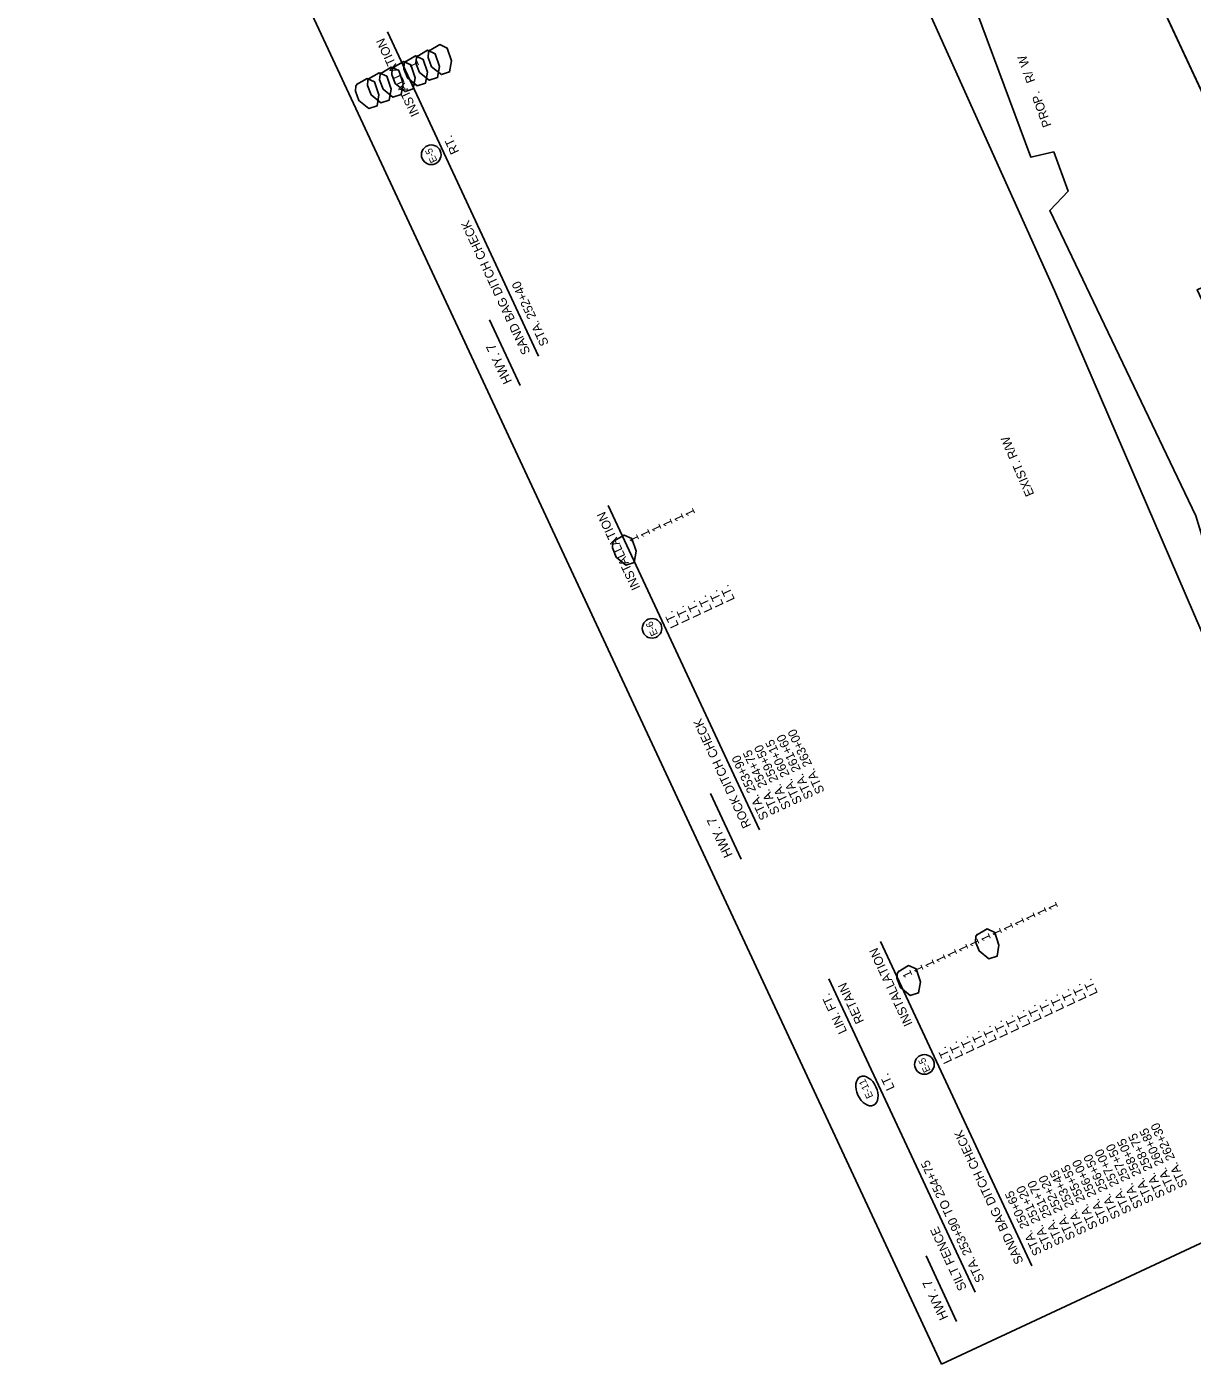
# Model space of a CAD drawing. Extents: x 964229 to 965790, y 1899262 to 1901149.
# Drawn here: x 964229 to 965014, y 1899262 to 1900163 of the extents above; entities that cross this region are included whole.
import ezdxf

# ---------------------------------------------------------------- set-up
doc = ezdxf.new("R2010")
doc.units = 0
for name, color, linetype in [('1', 7, 'Continuous'), ('44', 7, 'Continuous'), ('NO PLOT', 7, 'Continuous'), ('R_Draft', 7, 'Continuous'), ('S_TREE', 7, 'Continuous')]:
    doc.layers.add(name, color=color, linetype=linetype)

msp = doc.modelspace()

# ---------------------------------------------------------------- linework, layer by layer
at = {"layer": '1'}
msp.add_line((965070.98, 1900011.03), (964950.03, 1900270.4), dxfattribs=at)
for centre in [(964501.4, 1900076.83), (964650.13, 1899757.88), (964833.6, 1899464.18)]:
    msp.add_circle(centre, 6.61, dxfattribs=at)
msp.add_ellipse((964794.89, 1899446.28), major_axis=(-4.45, 9.53), ratio=0.638788, dxfattribs=at)
at = {"layer": '44'}
for p, q in [((964573.73, 1899941.19), (964471.87, 1900159.61)), ((964561.33, 1899921.41), (964540.69, 1899965.68)), ((964722.46, 1899622.24), (964620.6, 1899840.66)), ((964710.06, 1899602.46), (964689.42, 1899646.73)), ((964905.93, 1899328.54), (964804.07, 1899546.97)), ((964867.72, 1899310.72), (964769.33, 1899521.71)), ((964855.32, 1899290.95), (964834.68, 1899335.21))]:
    msp.add_line(p, q, dxfattribs=at)
at = {"layer": 'NO PLOT'}
for points in [[(965789.77, 1899702.74), (965115.54, 1901148.63), (964643.21, 1900928.38), (964770.42, 1900655.58), (964831.6, 1900684.11), (965011.21, 1900298.93), (964950.03, 1900270.4), (965070.98, 1900011.03), (965126.95, 1900037.14), (965271.77, 1899726.58), (965215.79, 1899700.48), (965317.44, 1899482.49)], [(965789.77, 1899702.74), (965115.54, 1901148.63), (964643.21, 1900928.38), (964770.42, 1900655.58), (964831.6, 1900684.11), (965011.21, 1900298.93), (964950.03, 1900270.4), (965070.98, 1900011.03), (965126.95, 1900037.14), (965271.77, 1899726.58), (965215.79, 1899700.48), (965317.44, 1899482.49)], [(965789.77, 1899702.74), (965115.54, 1901148.63), (964643.21, 1900928.38), (964770.42, 1900655.58), (964831.6, 1900684.11), (965011.21, 1900298.93), (964950.03, 1900270.4), (965070.98, 1900011.03), (965126.95, 1900037.14), (965271.77, 1899726.58), (965215.79, 1899700.48), (965317.44, 1899482.49)], [(965789.77, 1899702.74), (965115.54, 1901148.63), (964643.21, 1900928.38), (964770.42, 1900655.58), (964831.6, 1900684.11), (965011.21, 1900298.93), (964950.03, 1900270.4), (965070.98, 1900011.03), (965126.95, 1900037.14), (965271.77, 1899726.58), (965215.79, 1899700.48), (965317.44, 1899482.49)], [(964845.11, 1899262.24), (964344.7, 1900335.36), (964389.48, 1900356.24), (964306.73, 1900533.69), (964319.96, 1900539.86), (964228.89, 1900735.17), (964643.21, 1900928.38), (964770.42, 1900655.58), (964700.63, 1900623.04), (964880.25, 1900237.86), (964950.03, 1900270.4), (965070.98, 1900011.03), (965017.24, 1899985.98), (965162.05, 1899675.42), (965215.79, 1899700.48), (965317.44, 1899482.49)], [(964845.11, 1899262.24), (964344.7, 1900335.36), (964389.48, 1900356.24), (964306.73, 1900533.69), (964319.96, 1900539.86), (964228.89, 1900735.17), (964643.21, 1900928.38), (964770.42, 1900655.58), (964700.63, 1900623.04), (964880.25, 1900237.86), (964950.03, 1900270.4), (965070.98, 1900011.03), (965017.24, 1899985.98), (965162.05, 1899675.42), (965215.79, 1899700.48), (965317.44, 1899482.49)], [(964845.11, 1899262.24), (964344.7, 1900335.36), (964389.48, 1900356.24), (964306.73, 1900533.69), (964319.96, 1900539.86), (964228.89, 1900735.17), (964643.21, 1900928.38), (964770.42, 1900655.58), (964700.63, 1900623.04), (964880.25, 1900237.86), (964950.03, 1900270.4), (965070.98, 1900011.03), (965017.24, 1899985.98), (965162.05, 1899675.42), (965215.79, 1899700.48), (965317.44, 1899482.49)], [(964845.11, 1899262.24), (964344.7, 1900335.36), (964389.48, 1900356.24), (964306.73, 1900533.69), (964319.96, 1900539.86), (964228.89, 1900735.17), (964643.21, 1900928.38), (964770.42, 1900655.58), (964700.63, 1900623.04), (964880.25, 1900237.86), (964950.03, 1900270.4), (965070.98, 1900011.03), (965017.24, 1899985.98), (965162.05, 1899675.42), (965215.79, 1899700.48), (965317.44, 1899482.49)]]:
    msp.add_lwpolyline(points, close=True, dxfattribs=at)
msp.add_lwpolyline([(964743.2, 1900380.79), (964921.35, 1899985.44), (965071.82, 1899636.13), (965164.72, 1899429.12), (965178.4, 1899407.57), (965188.68, 1899415.47), (965049.43, 1899737.41), (965066.12, 1899749.34), (965054.6, 1899772.93), (965036.81, 1899766.7), (965016.41, 1899833.74), (964918.01, 1900039.22), (964930.54, 1900052.3), (964920.78, 1900078.79), (964905.36, 1900075.22), (964854.38, 1900212.3)], dxfattribs=at)
at = {"layer": 'S_TREE'}
for points in [[(964491.81, 1900143.09), (964498.95, 1900147.22), (964504, 1900144.92), (964506.91, 1900136.31), (964505.62, 1900128.79), (964500.05, 1900127.02), (964493.48, 1900132.35), (964491.07, 1900138.61), (964491.36, 1900142.31), (964492.44, 1900143.63)], [(964499.96, 1900146.9), (964507.1, 1900151.02), (964512.15, 1900148.72), (964515.06, 1900140.11), (964513.78, 1900132.59), (964508.21, 1900130.82), (964501.64, 1900136.16), (964499.23, 1900142.42), (964499.52, 1900146.11), (964500.6, 1900147.43)], [(964499.96, 1900146.9), (964507.1, 1900151.02), (964512.15, 1900148.72), (964515.06, 1900140.11), (964513.78, 1900132.59), (964508.21, 1900130.82), (964501.64, 1900136.16), (964499.23, 1900142.42), (964499.52, 1900146.11), (964500.6, 1900147.43)], [(964475.49, 1900135.49), (964482.63, 1900139.61), (964487.68, 1900137.31), (964490.59, 1900128.7), (964489.31, 1900121.18), (964483.74, 1900119.41), (964477.17, 1900124.75), (964474.76, 1900131.01), (964475.05, 1900134.7), (964476.13, 1900136.02)], [(964475.49, 1900135.49), (964482.63, 1900139.61), (964487.68, 1900137.31), (964490.59, 1900128.7), (964489.31, 1900121.18), (964483.74, 1900119.41), (964477.17, 1900124.75), (964474.76, 1900131.01), (964475.05, 1900134.7), (964476.13, 1900136.02)], [(964483.65, 1900139.29), (964490.79, 1900143.41), (964495.84, 1900141.11), (964498.75, 1900132.5), (964497.47, 1900124.98), (964491.89, 1900123.22), (964485.32, 1900128.55), (964482.91, 1900134.81), (964483.2, 1900138.5), (964484.29, 1900139.82)], [(964459.18, 1900127.88), (964466.32, 1900132), (964471.37, 1900129.7), (964474.28, 1900121.09), (964472.99, 1900113.57), (964467.42, 1900111.81), (964460.85, 1900117.14), (964458.44, 1900123.4), (964458.73, 1900127.09), (964459.82, 1900128.41)], [(964459.18, 1900127.88), (964466.32, 1900132), (964471.37, 1900129.7), (964474.28, 1900121.09), (964472.99, 1900113.57), (964467.42, 1900111.81), (964460.85, 1900117.14), (964458.44, 1900123.4), (964458.73, 1900127.09), (964459.82, 1900128.41)], [(964467.34, 1900131.68), (964474.48, 1900135.81), (964479.53, 1900133.5), (964482.44, 1900124.9), (964481.15, 1900117.38), (964475.58, 1900115.61), (964469.01, 1900120.94), (964466.6, 1900127.2), (964466.89, 1900130.9), (964467.97, 1900132.22)], [(964467.34, 1900131.68), (964474.48, 1900135.81), (964479.53, 1900133.5), (964482.44, 1900124.9), (964481.15, 1900117.38), (964475.58, 1900115.61), (964469.01, 1900120.94), (964466.6, 1900127.2), (964466.89, 1900130.9), (964467.97, 1900132.22)], [(964451.02, 1900124.08), (964458.16, 1900128.2), (964463.21, 1900125.9), (964466.12, 1900117.29), (964464.84, 1900109.77), (964459.27, 1900108), (964452.7, 1900113.34), (964450.29, 1900119.59), (964450.58, 1900123.29), (964451.66, 1900124.61)], [(964624.22, 1899816.54), (964631.36, 1899820.66), (964636.41, 1899818.36), (964639.32, 1899809.75), (964638.04, 1899802.23), (964632.47, 1899800.46), (964625.9, 1899805.8), (964623.49, 1899812.05), (964623.78, 1899815.75), (964624.86, 1899817.07)], [(964868.75, 1899551.31), (964875.89, 1899555.44), (964880.94, 1899553.13), (964883.85, 1899544.53), (964882.56, 1899537), (964876.99, 1899535.24), (964870.42, 1899540.57), (964868.01, 1899546.83), (964868.3, 1899550.52), (964869.38, 1899551.84)], [(964815.85, 1899526.64), (964822.99, 1899530.77), (964828.04, 1899528.47), (964830.95, 1899519.86), (964829.67, 1899512.34), (964824.09, 1899510.57), (964817.53, 1899515.9), (964815.11, 1899522.16), (964815.4, 1899525.86), (964816.49, 1899527.18)]]:
    msp.add_lwpolyline(points, dxfattribs=at)

# ---------------------------------------------------------------- texts
at = {"layer": '1'}
for s, rotation, p in [('E-5 ', 115, (964505.61, 1900072.73)), ('E-6 ', 115, (964654.22, 1899754.05)), ('E-5 ', 115, (964837.82, 1899460.08)), ('E-11', 114.99998, (964799.23, 1899442.56))]:
    msp.add_text(s, height=4.8, rotation=rotation, dxfattribs=at).set_placement(p)
at = {"layer": '44'}
for s, height, rotation, p in [('INSTALLATION', 6, 115, (964493.56, 1900104.23)), ('1', 6, 115, (964493.48, 1900136.8)), ('RT.', 6, 115, (964520.3, 1900078.87)), ('SAND BAG DITCH CHECK', 6, 115, (964568.3, 1899943.94)), ('STA. 252+40', 6, 115, (964580.69, 1899949.72)), ('HWY. 7', 6.25, 115, (964555.86, 1899924.2)), ('INSTALLATION', 6, 115, (964642.29, 1899785.28)), ('1', 6, 115, (964664.22, 1899828.11)), ('1', 6, 115, (964671.77, 1899831.63)), ('1', 6, 115, (964679.32, 1899835.15)), ('1', 6, 115, (964649.15, 1899821.09)), ('1', 6, 115, (964656.7, 1899824.61)), ('1', 6, 115, (964641.6, 1899817.56)), ('LT.', 6, 115, (964706.09, 1899777.36)), ('LT.', 6, 115, (964690.98, 1899770.31)), ('LT.', 6, 115, (964698.54, 1899773.84)), ('LT.', 6, 115, (964668.37, 1899759.77)), ('LT.', 6, 115, (964675.92, 1899763.29)), ('LT.', 6, 115, (964683.47, 1899766.81)), ('ROCK DITCH CHECK', 6, 115, (964717.03, 1899624.99)), ('STA. 263+00', 6, 115, (964766.53, 1899648.08)), ('STA. 259+50', 6, 115, (964743.92, 1899637.53)), ('STA. 260+15', 6, 115, (964751.43, 1899641.04)), ('STA. 261+60', 6, 115, (964758.98, 1899644.56)), ('STA. 253+90', 6, 115, (964728.81, 1899630.49)), ('STA. 254+75', 6, 115, (964736.36, 1899634.01)), ('HWY. 7', 6.25, 115, (964704.59, 1899605.25)), ('1', 6, 115, (964923.81, 1899569.91)), ('1', 6, 115, (964901.19, 1899559.37)), ('1', 6, 115, (964908.74, 1899562.89)), ('1', 6, 115, (964916.29, 1899566.41)), ('1', 6, 115, (964878.57, 1899548.82)), ('1', 6, 115, (964886.12, 1899552.34)), ('1', 6, 115, (964893.68, 1899555.86)), ('1', 6, 115, (964863.4, 1899541.74)), ('1', 6, 115, (964870.91, 1899545.25)), ('INSTALLATION', 6, 115, (964825.76, 1899491.58)), ('1', 6, 115, (964840.78, 1899531.2)), ('1', 6, 115, (964848.29, 1899534.7)), ('1', 6, 115, (964855.84, 1899538.22)), ('1', 6, 115, (964825.68, 1899524.15)), ('1', 6, 115, (964833.23, 1899527.67)), ('RETAIN', 6, 114.99998, (964793.02, 1899493.21)), ('LT.', 6, 115, (964943.06, 1899508.61)), ('LT.', 6, 115, (964950.61, 1899512.13)), ('LIN. FT.', 6, 114.99998, (964781.63, 1899486.46)), ('LT.', 6, 115, (964920.44, 1899498.06)), ('LT.', 6, 115, (964927.96, 1899501.57)), ('LT.', 6, 115, (964935.51, 1899505.09)), ('LT.', 6, 115, (964905.34, 1899491.02)), ('LT.', 6, 115, (964912.89, 1899494.54)), ('LT.', 6, 115, (964882.61, 1899480.42)), ('LT.', 6, 115, (964890.16, 1899483.94)), ('LT.', 6, 115, (964897.72, 1899487.47)), ('LT.', 6, 115, (964867.55, 1899473.4)), ('LT.', 6, 115, (964875.06, 1899476.9)), ('LT.', 6, 115, (964852.44, 1899466.36)), ('LT.', 6, 115, (964860, 1899469.88)), ('LT.', 6, 114.99998, (964813.77, 1899448.32)), ('SAND BAG DITCH CHECK', 6, 115, (964900.5, 1899331.3)), ('STA. 258+75', 6, 115, (964995.96, 1899375.81)), ('STA. 260+85', 6, 115, (965003.51, 1899379.33)), ('STA. 262+30', 6, 115, (965011.06, 1899382.85)), ('STA. 257+50', 6, 115, (964980.89, 1899368.79)), ('STA. 258+05', 6, 115, (964988.4, 1899372.29)), ('STA. 253+90 TO 254+75', 6, 114.99998, (964874.22, 1899319.04)), ('STA. 256+00', 6, 115, (964958.16, 1899358.19)), ('STA. 256+50', 6, 115, (964965.79, 1899361.74)), ('STA. 257+00', 6, 115, (964973.34, 1899365.26)), ('STA. 253+45', 6, 115, (964943.06, 1899351.14)), ('STA. 255+55', 6, 115, (964950.61, 1899354.67)), ('STA. 251+20', 6, 115, (964920.44, 1899340.6)), ('STA. 251+70', 6, 115, (964927.99, 1899344.12)), ('STA. 252+20', 6, 115, (964935.51, 1899347.62)), ('STA. 250+65', 6, 115, (964912.89, 1899337.08)), ('SILT FENCE      ', 6, 114.99998, (964862.29, 1899313.48)), ('HWY. 7', 6.25, 115, (964849.85, 1899293.74))]:
    msp.add_text(s, height=height, rotation=rotation, dxfattribs=at).set_placement(p)
at = {"layer": 'R_Draft'}
for s, rotation, p in [('W', 110.14627, (964904.42, 1900137.33)), ('/', 110.14627, (964906.44, 1900131.83)), ('R', 110.14627, (964908.39, 1900126.51)), ('P', 110.14627, (964913.42, 1900112.8)), ('O', 110.14627, (964915.44, 1900107.3)), ('.', 110.14627, (964911.47, 1900118.13)), ('R', 110.14627, (964917.39, 1900101.98)), ('P', 110.14627, (964919.34, 1900096.66)), ('EXIST. R/W', 113.66592, (964907.69, 1899848.3))]:
    msp.add_text(s, height=6, rotation=rotation, dxfattribs=at).set_placement(p)

doc.saveas('drawing.dxf')
